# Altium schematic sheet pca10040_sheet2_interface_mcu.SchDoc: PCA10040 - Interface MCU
size A3; Revision: 1.1.0; SheetNumber: 2; SheetTotal: 5; DrawnBy: KJP; ProjectNumber: 4397; PCAName: PCA10040; PCBRevision: 0071KJP; DocumentSize: A3; PCBNumber: 400150
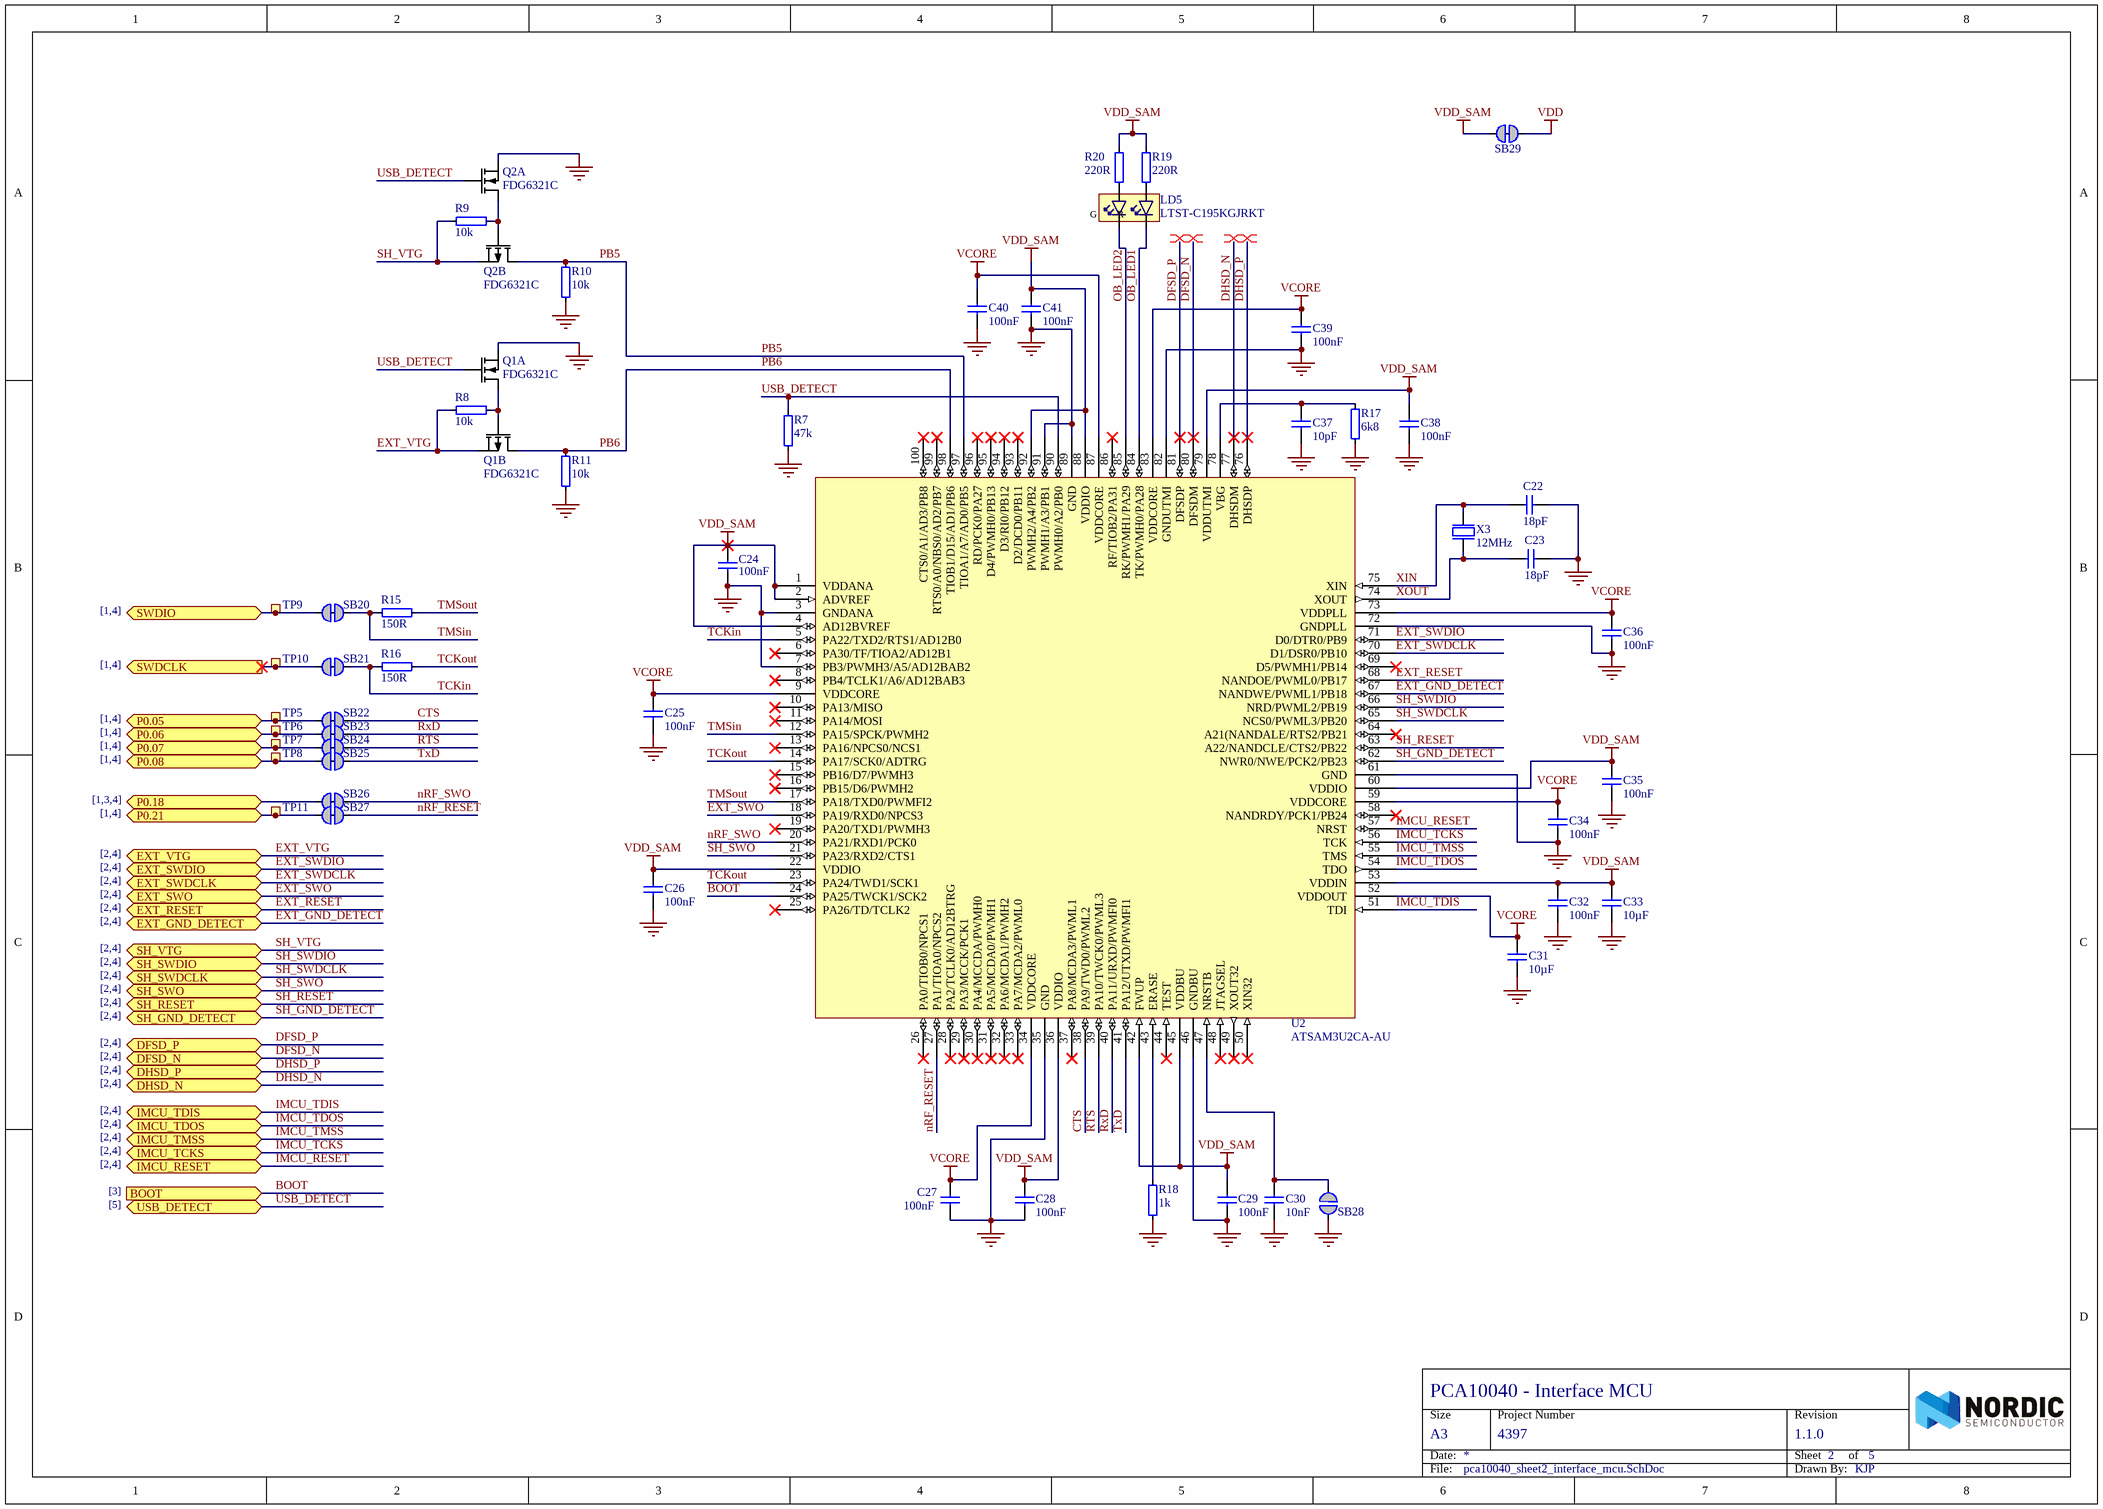
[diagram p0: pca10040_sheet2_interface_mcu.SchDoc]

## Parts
C22  18pF  [CAPC1005X04L]
C23  18pF  [CAPC1005X04L]
C24  100nF  [CAPC1005X04L]
C25  100nF  [CAPC1005X04L]
C26  100nF  [CAPC1005X04L]
C27  100nF  [CAPC1005X04L]
C28  100nF  [CAPC1005X04L]
C29  100nF  [CAPC1005X04L]
C30  10nF  [CAPC1005X04L]
C31  10µF  [CAPC1608X06L]
C32  100nF  [CAPC1005X04L]
C33  10µF  [CAPC1608X06L]
C34  100nF  [CAPC1005X04L]
C35  100nF  [CAPC1005X04L]
C36  100nF  [CAPC1005X04L]
C37  10pF  [CAPC1005X04L]
C38  100nF  [CAPC1005X04L]
C39  100nF  [CAPC1005X04L]
C40  100nF  [CAPC1005X04L]
C41  100nF  [CAPC1005X04L]
LD5  LTST-C195KGJRKT  [LED_DUAL_0606]
Q1  FDG6321C  [SOT65P210X100-6N]  (parts A,B of 2)
Q2  FDG6321C  [SOT65P210X100-6N]  (parts A,B of 2)
R7  47k  [RESC1005X04L]
R8  10k  [RESC1005X04L]
R9  10k  [RESC1005X04L]
R10  10k  [RESC1005X04L]
R11  10k  [RESC1005X04L]
R15  150R  [RESC1005X04L]
R16  150R  [RESC1005X04L]
R17  6k8  [RESC1005X04L]
R18  1k  [RESC1005X04L]
R19  220R  [RESC1005X04L]
R20  220R  [RESC1005X04L]
SB20  Solderbridge  [Solderbridge_Shorted]  (value not drawn)  (net tie, no BOM)
SB21  Solderbridge  [Solderbridge_Shorted]  (value not drawn)  (net tie, no BOM)
SB22  Solderbridge  [Solderbridge_Shorted]  (value not drawn)  (net tie, no BOM)
SB23  Solderbridge  [Solderbridge_Shorted]  (value not drawn)  (net tie, no BOM)
SB24  Solderbridge  [Solderbridge_Shorted]  (value not drawn)  (net tie, no BOM)
SB25  Solderbridge  [Solderbridge_Shorted]  (value not drawn)  (net tie, no BOM)
SB26  Solderbridge  [Solderbridge_Shorted]  (value not drawn)  (net tie, no BOM)
SB27  Solderbridge  [Solderbridge_Shorted]  (value not drawn)  (net tie, no BOM)
SB28  Solderbridge  [Solderbridge]  (value not drawn)  (no BOM)
SB29  Solderbridge  [Solderbridge_Shorted]  (value not drawn)  (net tie, no BOM)
TP5  Ø1.0mm,SMD  [TP_SMD_Ø1.0mm]  (value not drawn)  (no BOM)
TP6  Ø1.0mm,SMD  [TP_SMD_Ø1.0mm]  (value not drawn)  (no BOM)
TP7  Ø1.0mm,SMD  [TP_SMD_Ø1.0mm]  (value not drawn)  (no BOM)
TP8  Ø1.0mm,SMD  [TP_SMD_Ø1.0mm]  (value not drawn)  (no BOM)
TP9  Ø1.0mm,SMD  [TP_SMD_Ø1.0mm]  (value not drawn)  (no BOM)
TP10  Ø1.0mm,SMD  [TP_SMD_Ø1.0mm]  (value not drawn)  (no BOM)
TP11  Ø1.0mm,SMD  [TP_SMD_Ø1.0mm]  (value not drawn)  (no BOM)
U2  ATSAM3U2CA-AU  [TSQFP50P1600X1600X160-100N]
X3  12MHz  [BT-XTAL_3225]

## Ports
BOOT (in), DFSD_N (bidir), DFSD_P (bidir), DHSD_N (bidir), DHSD_P (bidir), EXT_GND_DETECT (bidir), EXT_RESET (bidir), EXT_SWDCLK (bidir), EXT_SWDIO (bidir), EXT_SWO (bidir), EXT_VTG (bidir), IMCU_RESET (bidir), IMCU_TCKS (bidir), IMCU_TDIS (bidir), IMCU_TDOS (bidir), IMCU_TMSS (bidir), P0.05 (bidir), P0.06 (bidir), P0.07 (bidir), P0.08 (bidir), P0.18 (bidir), P0.21 (bidir), SH_GND_DETECT (bidir), SH_RESET (bidir), SH_SWDCLK (bidir), SH_SWDIO (bidir), SH_SWO (bidir), SH_VTG (bidir), SWDCLK (out), SWDIO (bidir), USB_DETECT (bidir)

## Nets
GND: C22.2 C23.2 C24.1 C25.1 C26.1 C27.1 C28.1 C29.1 C30.1 C31.1 C32.1 C33.1 C34.1 C35.1 C36.2 C37.1 C38.1 C39.1 C40.1 C41.1 Q1.1(S1) Q2.1(S1) R7.2 R10.1 R11.1 R17.1 R18.1 SB28.2 U2.3(GNDANA) U2.7(PB3/PWMH3/A5/AD12BAB2) U2.35(GND) U2.46(GNDBU) U2.61(GND) U2.72(GNDPLL) U2.82(GNDUTMI) U2.89(GND) U2.91(PWMH1/A3/PB1) X3.2(GND) X3.4(GND)
VCORE: C25.2 C27.2 C31.2 C34.2 C36.1 C39.2 C40.2 U2.9(VDDCORE) U2.34(VDDCORE) U2.52(VDDOUT) U2.59(VDDCORE) U2.73(VDDPLL) U2.83(VDDCORE) U2.87(VDDCORE)
VDD: SB29.2
VDD_SAM: C24.2 C26.2 C28.2 C29.2 C32.2 C33.2 C35.2 C38.2 C41.2 R19.2 R20.2 SB29.1 U2.1(VDDANA) U2.2(ADVREF) U2.4(AD12BVREF) U2.22(VDDIO) U2.36(VDDIO) U2.42(FWUP) U2.45(VDDBU) U2.53(VDDIN) U2.60(VDDIO) U2.79(VDDUTMI) U2.88(VDDIO) U2.92(PWMH2/A4/PB2)
BOOT: U2.24(PA25/TWCK1/SCK2) ; port BOOT
CTS: SB22.2 U2.38(PA9/TWD0/PWML2)
DFSD_N: U2.80(DFSDM) ; port DFSD_N
DFSD_P: U2.81(DFSDP) ; port DFSD_P
DHSD_N: U2.77(DHSDM) ; port DHSD_N
DHSD_P: U2.76(DHSDP) ; port DHSD_P
EXT_GND_DETECT: U2.67(NANDWE/PWML1/PB18) ; port EXT_GND_DETECT
EXT_RESET: U2.68(NANDOE/PWML0/PB17) ; port EXT_RESET
EXT_SWDCLK: U2.70(D1/DSR0/PB10) ; port EXT_SWDCLK
EXT_SWDIO: U2.71(D0/DTR0/PB9) ; port EXT_SWDIO
EXT_SWO: U2.18(PA19/RXD0/NPCS3) ; port EXT_SWO
EXT_VTG: Q1.4(S2) R8.1 ; port EXT_VTG
IMCU_RESET: U2.57(NRST) ; port IMCU_RESET
IMCU_TCKS: U2.56(TCK) ; port IMCU_TCKS
IMCU_TDIS: U2.51(TDI) ; port IMCU_TDIS
IMCU_TDOS: U2.54(TDO) ; port IMCU_TDOS
IMCU_TMSS: U2.55(TMS) ; port IMCU_TMSS
nRF_RESET: SB27.2 U2.27(PA1/TIOA0/NPCS2)
nRF_SWO: SB26.2 U2.20(PA21/RXD1/PCK0)
OB_LED1: LD5.4(C1) U2.84(TK/PWMH0/PA28)
OB_LED2: LD5.3(C2) U2.85(RK/PWMH1/PA29)
P0.05: SB22.1 TP5.1 ; port P0.05
P0.06: SB23.1 TP6.1 ; port P0.06
P0.07: SB24.1 TP7.1 ; port P0.07
P0.08: SB25.1 TP8.1 ; port P0.08
P0.18: SB26.1 ; port P0.18
P0.21: SB27.1 TP11.1 ; port P0.21
PB5: Q2.3(D2) R10.2 U2.97(TIOA1/A7/AD0/PB5)
PB6: Q1.3(D2) R11.2 U2.98(TIOB1/D15/AD1/PB6)
RTS: SB24.2 U2.39(PA10/TWCK0/PWML3)
RxD: SB23.2 U2.40(PA11/URXD/PWMFI0)
SH_GND_DETECT: U2.62(NWR0/NWE/PCK2/PB23) ; port SH_GND_DETECT
SH_RESET: U2.63(A22/NANDCLE/CTS2/PB22) ; port SH_RESET
SH_SWDCLK: U2.65(NCS0/PWML3/PB20) ; port SH_SWDCLK
SH_SWDIO: U2.66(NRD/PWML2/PB19) ; port SH_SWDIO
SH_SWO: U2.21(PA23/RXD2/CTS1) ; port SH_SWO
SH_VTG: Q2.4(S2) R9.1 ; port SH_VTG
SWDCLK: SB21.1 TP10.1 ; port SWDCLK
SWDIO: SB20.1 TP9.1 ; port SWDIO
TCKin: R16.2 SB21.2 U2.5(PA22/TXD2/RTS1/AD12B0)
TCKout: R16.1 U2.14(PA17/SCK0/ADTRG) U2.23(PA24/TWD1/SCK1)
TMSin: R15.2 SB20.2 U2.12(PA15/SPCK/PWMH2)
TMSout: R15.1 U2.17(PA18/TXD0/PWMFI2)
TxD: SB25.2 U2.41(PA12/UTXD/PWMFI1)
USB_DETECT: Q1.2(G1) Q2.2(G1) R7.1 U2.90(PWMH0/A2/PB0) ; port USB_DETECT
XIN: C22.1 U2.75(XIN) X3.3(out)
XOUT: C23.1 U2.74(XOUT) X3.1(inp)
NetC30_2: C30.2 SB28.1 U2.47(NRSTB)
NetC37_2: C37.2 R17.2 U2.78(VBG)
NetLD5_1: LD5.1(A2) R20.1
NetLD5_2: LD5.2(A1) R19.1
NetQ1_5: Q1.5(G2) Q1.6(D1) R8.2
NetQ2_5: Q2.5(G2) Q2.6(D1) R9.2
NetR18_2: R18.2 U2.43(ERASE)

Not connected (* = marked no-connect by the designer): U2 6(PA30/TF/TIOA2/AD12B1)* 8(PB4/TCLK1/A6/AD12BAB3)* 10(PA13/MISO)* 11(PA14/MOSI)* 13(PA16/NPCS0/NCS1)* 15(PB16/D7/PWMH3)* 16(PB15/D6/PWMH2)* 19(PA20/TXD1/PWMH3)* 25(PA26/TD/TCLK2)* 26(PA0/TIOB0/NPCS1)* 28(PA2/TCLK0/AD12BTRG)* 29(PA3/MCCK/PCK1)* 30(PA4/MCCDA/PWMH0)* 31(PA5/MCDA0/PWMH1)* 32(PA6/MCDA1/PWMH2)* 33(PA7/MCDA2/PWML0)* 37(PA8/MCDA3/PWML1)* 44(TEST)* 48(JTAGSEL)* 49(XOUT32)* 50(XIN32)* 58(NANDRDY/PCK1/PB24)* 64(A21(NANDALE/RTS2/PB21)* 69(D5/PWMH1/PB14)* 86(RF/TIOB2/PA31)* 93(D2/DCD0/PB11)* 94(D3/RI0/PB12)* 95(D4/PWMH0/PB13)* 96(RD/PCK0/PA27)* 99(RTS0/A0/NBS0/AD2/PB7)* 100(CTS0/A1/AD3/PB8)*

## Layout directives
differential pair: DFSD_N, DFSD_P, DHSD_N, DHSD_P

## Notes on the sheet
- [1,4]
- [1,3,4]
- [2,4]
- [3]
- [5]

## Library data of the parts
C22 C23 = C0402-18p: Capacitor, NP0, ±5%; Note: 50V; Artikkelnr Noca: 20029209; Artikkelnr Simpro: N.A.
C24-C29 C32 C34-C36 C38-C41 = C0402-100n: Capacitor, X7R, ±10%; Note: 16V; Artikkelnr Noca: 20039200; Artikkelnr Simpro: N.A.
C30 = C0402-10n: Capacitor, X7R, ±10%; Note: 16V; Artikkelnr Noca: 20039166; Artikkelnr Simpro: N.A.
C31 C33 = C0603-10µ: Capacitor, X5R, ±20%; Note: 6.3V; Artikkelnr Noca: 20039234; Artikkelnr Simpro: N.A.
C37 = C0402-10p: Capacitor, NP0, ±2%; 2nd source part number: 185-6064; Note: 50V; Artikkelnr Noca: 20029260; Artikkelnr Simpro: N.A.
LD5 = LTST-C195KGJRKT: Ultra bright AlInGaP Bi-Color LED; Manufacturer: Lite-On Inc; 2nd source part number: 859-LTST-C195KGJRKT; Artikkelnr Noca: 13019145; Artikkelnr Simpro: N.A.
Q1 Q2 = FDG6321C_IPC: Fairchild, FDG6321C, Dual N & P Channel Digital FET; 2nd source part number: FDG6321CCT-ND; Artikkelnr Noca: 35029089; Artikkelnr Simpro: N.A.
R7 = R0402-47k: Resistor, ±1%, 0.063W; Note: Chip Res 1%; Artikkelnr Noca: 27049113; Artikkelnr Simpro: N.A.
R8-R11 = R0402-10k: Resistor, ±1%, 0.063W; Note: Chip Res 1%; Artikkelnr Noca: 27049097; Artikkelnr Simpro: N.A.
R15 R16 = R0402-150: Resistor, ±1%, 0.063W; Note: Chip Res 1%; Artikkelnr Noca: 27049053; Artikkelnr Simpro: N.A.
R17 = R0402-6k8: Resistor, ±1%, 0.063W; Note: Chip Res 1%; Artikkelnr Noca: 27049093; Artikkelnr Simpro: N.A.
R18 = R0402-1k0: Resistor, ±1%, 0.063W; Note: Chip Res 1%; Artikkelnr Noca: 27049073; Artikkelnr Simpro: N.A.
R19 R20 = R0402-220: Resistor, ±1%, 0.063W; Note: Chip Res 1%; Artikkelnr Noca: 27049057; Artikkelnr Simpro: N.A.
SB20-SB27 SB29 = Solderbridge Shorted: Shorted Solderbridge; Artikkelnr Noca: N.A.
SB28 = Solderbridge: Artikkelnr Noca: N.A.
TP5-TP11 = TP_SMD_Ø1.0MM: 1.0mm circular SMD testpad; Manufacturer: Nordic Semiconductor; Artikkelnr Noca: N.A.
U2 = ATSAM3U2CA-AU: IC MCU 32bit 128kB flash 100LQFP; Manufacturer: Atmel; 2nd source part number: 184-1662; Artikkelnr Noca: 15019073; Artikkelnr Simpro: N.A.
X3 = XTAL SMD 12MHz (3225): XTAL SMD 3225, 12MHz, 18pF, ±30ppm; Manufacturer: TXC Corporation; Manufacturer Part Number: 7M-12.000MAAJ-T; 2nd source part number: 184-2056; Note: XTAL SMD 12.000MHz; Artikkelnr Noca: 22019166; Artikkelnr Simpro: N.A.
